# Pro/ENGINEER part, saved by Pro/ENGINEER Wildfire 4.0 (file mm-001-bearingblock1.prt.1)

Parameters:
  METRIC = "NO"

Other parameters: PITCH, DRILL_POINT_ANGLE, DRILL_DEPTH, DRILL_DIAMETER, THREAD_DIAMETER, THREADS_PER_INCH, THREAD_DEPTH, THREAD_LENGTH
